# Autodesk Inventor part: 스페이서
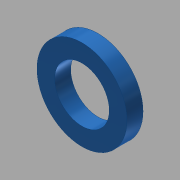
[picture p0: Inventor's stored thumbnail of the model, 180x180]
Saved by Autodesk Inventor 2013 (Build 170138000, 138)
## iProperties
Created: 2018-01
Part Number: 스페이서
Material: 스테인리스강
Document SubType Name: Modeling
Designer: mduedu
Density: 1 g/cm^3
Author: mduedu
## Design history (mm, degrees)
sketch "스케치1"
  geometry: C1 r 7 at (0, 0); C2 r 4.25 at (0, 0); 1 further point
  constraints: 2 centre point, 2 coincident
  dimensions: "d0" = 14 diameter of C1; "d1" = 8.5 diameter of C2
extrude "돌출1" new body sketch "스케치1" distance "d2" = 2.5; taper "d3" = 0 deg
node "솔리드1"
